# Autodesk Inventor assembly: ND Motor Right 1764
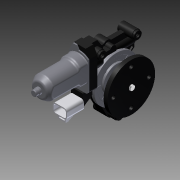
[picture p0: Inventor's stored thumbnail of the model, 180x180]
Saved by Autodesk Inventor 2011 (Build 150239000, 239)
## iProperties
Shininess: 64.0
Length Units: 11272
Angle Units: 11279
Time Units: 11290
Mass Units: 11286
Length Display Precision: 3
Angle Display Precision: 2
Compacted: True
Part Number: ND Motor Right 1764
Document SubType Name: Assembly
Created: 2006-01
Designer: Ed Sparks
Density: 0.0
Volumn: 0.0
Area: 0.0
PropertySet Name: Model Information
Control State: 0
Master: False
Checked Out: False
Author: Ed Sparks
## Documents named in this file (3)
- R:\CAD Archives\Motors\ND Motor Right 1764\ND Motor Right 1764.iam
- R:\CAD Archives\Motors\ND Motor Right 1764\ND Motor Right 1764.ipt
- R:\CAD Archives\Motors\ND Motor Right 1764\Window Motor Coupler 2 1764.ipt
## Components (2 placed, 2 different names)
1. ND Motor Right 1764:1 — Angle:1, Mate:2, Mate:3, Mate:4
2. Window Motor Coupler 2 1764:1 — Angle:1, Mate:2, Mate:3, Mate:4
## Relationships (4: Mate 3, Angle 1)
- Angle:1: ND Motor Right 1764:1 ↔ Window Motor Coupler 2 1764:1
- Mate:2: ND Motor Right 1764:1 ↔ Window Motor Coupler 2 1764:1
- Mate:3: ND Motor Right 1764:1 ↔ Window Motor Coupler 2 1764:1
- Mate:4: ND Motor Right 1764:1 ↔ Window Motor Coupler 2 1764:1
